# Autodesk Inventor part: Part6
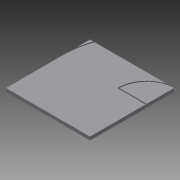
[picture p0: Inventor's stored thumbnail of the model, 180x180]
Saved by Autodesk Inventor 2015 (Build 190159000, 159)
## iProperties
Created: 2015-04
Part Number: Part6
Material: Generic
Document SubType Name: Modeling
Designer: TREINA5
Density: 1 g/cm^3
Appearance: Default
Mass: 129607 g
Surface Area: 48393.7 cm^2
Volume: 129607 cm^3
Author: TREINA5
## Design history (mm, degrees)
sketch "Sketch1"
  geometry: L1 (2980, 10480)-(2980, 11220); L2 (3000, 12020)-(3000, 11220); L3 (2980, 11220)-(2980, 12020); L4 (2000, 11220)-(2000, 11200); L5 (2980, 11980)-(1500, 11980); L6 (1500, 10480)-(2980, 10480); L7 (1500, 11220)-(1500, 10480); L8 (2000, 11200)-(1500, 11200); L9 (6000, 7500)-(6000, 8980); L10 (6000, 10480)-(7480, 10480); L11 (6000, 9000)-(7480, 9000); L12 (6000, 8980)-(7480, 8980); L13 (6000, 7500)-(7480, 7500); L14 (6000, 7480)-(7480, 7480); L15 (2980, 4979.966)-(2980, 4500); L16 (3000, 4479.966)-(3479.966, 4479.966); L17 (1500, 4500)-(2480.132, 4500); L18 (1500, 4479.966)-(2980, 4479.966); L19 (1500, 4500)-(2980, 4500); L20 (2500.034, 4500)-(2980, 4500); L21 (2980, 4479.966)-(2980, 3999.933); L22 (3000, 4000.034)-(3000, 4479.966); L23 (5500.034, 4499.966)-(5980, 4499.966); L24 (5500, 4479.966)-(5980, 4479.966); L25 (4500, 5979.966)-(5745.054, 5979.966); L26 (4500, 4734.913)-(4500, 5979.966); L27 (4500, 4499.966)-(5480.132, 4499.966); L28 (4500, 4479.966)-(5480, 4479.966); L29 (2980, 5980)-(2980, 4500); L30 (2980, 5980)-(2980, 4999.868); L31 (3000, 4999.868)-(3000, 5979.966); L32 (3000, 4734.98)-(3000, 5980.034); L33 (4480, 5979.966)-(4480, 4734.946); L34 (3235.15, 5979.966)-(4480, 5979.966); L35 (4480, 6000)-(3000, 6000); L36 (1500, 6000)-(1500, 7480); L37 (1500, 7480)-(2980, 7480); L38 (2980, 7480)-(2980, 6000); L39 (1500, 7480)-(2980, 7480); L40 (2980, 7480)-(2980, 6000); L41 (1500, 5980)-(2745.054, 5980); L42 (2980, 6000)-(1500, 6000); L43 (3000, 7480)-(4480, 7480); L44 (4480, 7480)-(4480, 6000); L45 (3000, 6000)-(3000, 7480); L46 (3000, 7500)-(4480, 7500); L47 (5980, 7480)-(5980, 6000); L48 (4500, 6000)-(4500, 7480); L49 (6000, 6000)-(6000, 7480); L50 (5980, 6000)-(4500, 6000); L51 (2980, 8980)-(2980, 7500); L52 (1500, 7500)-(2980, 7500); L53 (2980, 8980)-(2980, 7500); L54 (1500, 7500)-(2980, 7500); L55 (3000, 7500)-(3000, 8980); L56 (1500, 8980)-(2570.717, 8980); L57 (1500, 7909.283)-(1500, 8980); L58 (1500, 7909.283)-(1500, 8980); L59 (1480, 8980.017)-(1480, 7897.684); L60 (1500, 8980)-(2570.717, 8980); L61 (4500, 10480)-(5980, 10480); L62 (5980, 8980)-(5980, 7500); L63 (4500, 7480)-(5980, 7480); L64 (6000, 10480)-(6000, 9000)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; A1 r 1510 centre (4490, 4490.034) between (2980.033, 4500) and (2980.034, 4480); A2 r 490.068 centre (2990, 4490) between (3479.967, 4499.966) and (3000, 4979.966); A3 r 509.966 centre (2990, 4490) between (3499.869, 4499.966) and (3000, 4999.868); A4 r 1510 centre (2990, 4490) between (2745.054, 5980) and (1500, 4734.946); A5 r 1490.034 centre (2990, 4490) between (2980, 5980) and (1500, 4500); A6 r 509.966 centre (2990, 4490) between (2980, 4999.868) and (2480.131, 4499.966); A7 r 490.068 centre (2990, 4490) between (2980, 4979.966) and (2500.033, 4499.966); A8 r 490.068 centre (5990, 4489.966) between (5980, 4979.933) and (5500.033, 4499.932); A9 r 509.966 centre (5990, 4489.966) between (5980, 4999.835) and (5480.131, 4499.932); A10 r 1490.034 centre (5990, 4489.966) between (5980, 5979.966) and (4500, 4499.966); A11 r 1510 centre (5990, 4489.966) between (5745.054, 5979.966) and (4500, 4734.913); A12 r 1510 centre (2990, 4490) between (4490.002, 4663.473) and (4489.998, 4663.506); A13 r 1510 centre (2990, 4490) between (4499.967, 4499.966) and (4499.966, 4500.033); A14 r 1510 centre (5990, 4489.966) between (4490.002, 4663.473) and (4489.998, 4663.439); A15 r 1490.034 centre (2990, 4490) between (4480, 4500) and (3000, 5980); A16 r 1510 centre (2990, 4490) between (4480, 4734.946) and (3235.15, 5979.966); A17 r 2990 centre (-10, 10490) between (1500, 7909.302) and (2570.698, 8980); A18 r 3010 centre (-10, 10490) between (1500, 7886.157) and (2593.843, 8980); A19 r 3010 centre (-10, 10490) between (336.554, 7500.017) and (1500, 7886.157); A20 r 2990 centre (-10, 10490) between (-0.017, 7500.017) and (1480, 7897.704); A21 r 2990 centre (-10, 10490) between (-19.983, 7500.017) and (1500, 7909.302); A22 r 3010 centre (-10, 10490) between (2605.339, 9000) and (2980, 10143.59); A23 r 2990 centre (-10, 10490) between (2582.296, 9000) and (2979.983, 10480); A24 r 490.068 centre (11990, 4489.966) between (12479.967, 4499.932) and (12000, 4979.933); A25 r 509.966 centre (11990, 4489.966) between (12499.869, 4499.932) and (12000, 4999.835); A26 r 1490.034 centre (11990, 4489.966) between (13480, 4499.966) and (12000, 5979.966); A27 r 1510 centre (11990, 4489.966) between (13480, 4734.913) and (12234.946, 5979.966); A28 r 490.068 centre (11990, 2989.966) between (12479.967, 2999.932) and (12000, 3479.933); A29 r 509.966 centre (11990, 2989.966) between (12499.869, 2999.932) and (12000, 3499.835); A30 r 490.068 centre (11990, 4489.966) between (12000, 4000) and (12479.967, 4480.001); A31 r 509.966 centre (11990, 4489.966) between (12000, 3980.098) and (12499.869, 4480.001); A32 r 1510 centre (11990, 2990.034) between (12234.538, 1499.966) and (13480, 2745.087); A33 r 1490.034 centre (11990, 2990.034) between (12000, 1500.034) and (13480, 2979.966); A34 r 509.966 centre (11990, 2989.966) between (12000, 2480.098) and (12499.869, 2980.001); A35 r 490.068 centre (11990, 2989.966) between (12000, 2500) and (12479.967, 2980.001); A36 r 490.068 centre (11990, 2989.966) between (11500.033, 2980.001) and (11980, 2500); A37 r 1490.034 centre (11990, 2990.034) between (13480, 2999.966) and (13277.536, 3740); A38 r 1510 centre (11990, 2990.034) between (13480, 3234.98) and (13300.591, 3740); A39 r 1510 centre (11990, 4489.966) between (13300.591, 3740) and (13480, 4245.02); A40 r 1490.034 centre (11990, 4489.966) between (13277.537, 3740) and (13480, 4479.966); A41 r 4510.011 centre (14990, 5990) between (14979.989, 1480) and (14980, 1480); A42 r 509.966 centre (5990, 2989.966) between (6000, 2480.098) and (6499.869, 2980.001); A43 r 490.068 centre (5990, 2989.966) between (6000, 2500) and (6479.967, 2980.001); A44 r 1510 centre (5990, 2989.966) between (7499.966, 2999.966) and (7499.966, 3000); A45 r 1490.034 centre (5990, 2989.966) between (6000, 1499.966) and (7480, 2979.966); A46 r 1510 centre (5990, 2989.966) between (6234.946, 1499.966) and (7480, 2745.02); A47 r 1510 centre (11990, 4489.966) between (11745.054, 5979.966) and (10500, 4734.913); A48 r 1490.034 centre (11990, 4489.966) between (11980, 5979.966) and (10500, 4499.966); A49 r 490.068 centre (11990, 4489.966) between (11980, 4979.933) and (11500.033, 4499.932); A50 r 509.966 centre (11990, 4489.966) between (11980, 4999.835) and (11480.131, 4499.932); A51 r 1510 centre (11990, 2990.034) between (10500, 2745.087) and (11745.258, 1500); A52 r 1490.034 centre (11990, 2990.034) between (10500, 2980.034) and (11980, 1500.034); A53 r 509.966 centre (11990, 2989.966) between (11480.131, 2980.001) and (11980, 2480.098); A54 r 1510 centre (11990, 2990.034) between (10480.034, 3000.067) and (10480.033, 2999.966); A55 r 1510 centre (11990, 4489.966) between (10480.034, 4479.966) and (10480.034, 4479.933); A56 r 1510 centre (5990, 4489.966) between (7499.966, 4479.933) and (7499.966, 4479.966); A57 r 490.068 centre (5990, 4489.966) between (6479.967, 4499.932) and (6000, 4979.933); A58 r 509.966 centre (5990, 4489.966) between (6499.869, 4499.932) and (6000, 4999.835); A59 r 1510 centre (5990, 4489.966) between (7480, 4734.913) and (6234.946, 5979.966); A60 r 1490.034 centre (5990, 4489.966) between (7480, 4499.966) and (6000, 5979.966); A61 r 3010.067 centre (13489.917, 8990) between (10500, 8642.293) and (10874.958, 7499.198); A62 r 2989.933 centre (13489.917, 8990) between (10500, 8980) and (10898.159, 7499.198); A63 r 3010.067 centre (13489.917, 8990) between (12000, 6374.536) and (13149.912, 5999.198); A64 r 2989.933 centre (13489.917, 8990) between (12000, 6397.733) and (13479.998, 6000.083)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; 7 further points
  constraints: 980 end point, 212 point on circle, 98 point on line, 89 centre point, 6 parallel, 2 collinear, 2 perpendicular, 1 coincident, 1 horizontal, 24 other
  dimensions: "d0" = 20 distance between parallel lines of L425 L426
extrude "Extrusion1" new body sketch "Sketch1" distance "d1" = 60; taper "d2" = 0 deg
extrude "Extrusion2" new body sketch "Sketch1" distance "d3" = 60; taper "d4" = 0 deg
extrude "Extrusion3" new body sketch "Sketch1" distance "d5" = 60; taper "d6" = 0 deg
body "Solid1"
body "Solid2"
body "Solid3"
